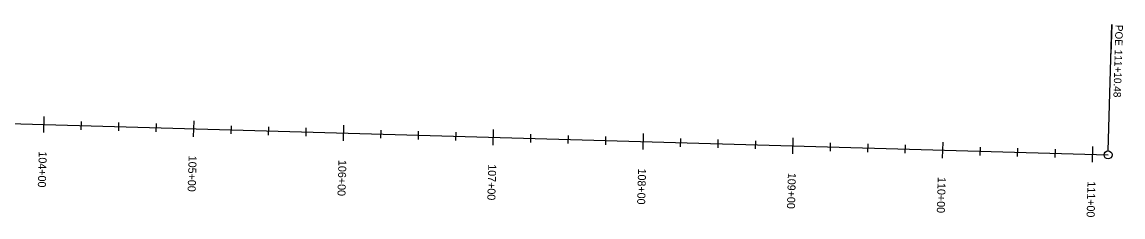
# Model space of a CAD drawing. Extents: x 2301963 to 2307911, y 760768 to 761974.
# Drawn here: x 2307177 to 2307911, y 760768 to 760898 of the extents above; entities that cross this region are included whole.
import ezdxf

# ---------------------------------------------------------------- set-up
doc = ezdxf.new("R2010")
doc.units = 0
for name, color, linetype in [('Default', 7, 'Continuous'), ('Draft_Station Cardinal Points', 7, 'Continuous'), ('Draft_Station Labels Major', 7, 'Continuous'), ('Draft_Station Ticks Major', 7, 'Continuous'), ('Draft_Station Ticks Minor', 7, 'Continuous'), ('Geom_Secondary', 7, 'Continuous')]:
    doc.layers.add(name, color=color, linetype=linetype)

msp = doc.modelspace()

# ---------------------------------------------------------------- linework, layer by layer
at = {"layer": 'Default'}
msp.add_line((2304792.58, 760898.19), (2307901.31, 760809.5), dxfattribs=at)
at = {"layer": 'Draft_Station Cardinal Points'}
for p, q in [((2307901.39, 760812.17), (2307903.79, 760896.47)), ((2307903.79, 760896.47), (2307903.23, 760876.79)), ((2307901.31, 760809.5), (2307901.31, 760809.5))]:
    msp.add_line(p, q, dxfattribs=at)
msp.add_circle((2307901.31, 760809.5), 2.67, dxfattribs=at)
at = {"layer": 'Draft_Station Ticks Major'}
for p, q in [((2307191.27, 760835.1), (2307190.97, 760824.48)), ((2307291.23, 760832.25), (2307290.93, 760821.63)), ((2307391.19, 760829.4), (2307390.89, 760818.78)), ((2307491.15, 760826.54), (2307490.84, 760815.93)), ((2307591.11, 760823.69), (2307590.8, 760813.08)), ((2307691.07, 760820.84), (2307690.76, 760810.23)), ((2307791.03, 760817.99), (2307790.72, 760807.37)), ((2307890.98, 760815.14), (2307890.68, 760804.52))]:
    msp.add_line(p, q, dxfattribs=at)
at = {"layer": 'Draft_Station Ticks Minor'}
for p, q in [((2307216.19, 760831.81), (2307216.03, 760826.29)), ((2307241.18, 760831.1), (2307241.02, 760825.58)), ((2307266.17, 760830.38), (2307266.01, 760824.86)), ((2307316.15, 760828.96), (2307315.99, 760823.44)), ((2307341.13, 760828.24), (2307340.98, 760822.73)), ((2307366.12, 760827.53), (2307365.97, 760822.01)), ((2307416.1, 760826.1), (2307415.95, 760820.59)), ((2307441.09, 760825.39), (2307440.94, 760819.87)), ((2307466.08, 760824.68), (2307465.93, 760819.16)), ((2307516.06, 760823.25), (2307515.91, 760817.73)), ((2307541.05, 760822.54), (2307540.9, 760817.02)), ((2307566.04, 760821.83), (2307565.89, 760816.31)), ((2307616.02, 760820.4), (2307615.87, 760814.88)), ((2307641.01, 760819.69), (2307640.86, 760814.17)), ((2307666, 760818.98), (2307665.85, 760813.46)), ((2307715.98, 760817.55), (2307715.82, 760812.03)), ((2307740.97, 760816.84), (2307740.81, 760811.32)), ((2307765.96, 760816.12), (2307765.8, 760810.61)), ((2307815.94, 760814.7), (2307815.78, 760809.18)), ((2307840.93, 760813.98), (2307840.77, 760808.47)), ((2307865.92, 760813.27), (2307865.76, 760807.75))]:
    msp.add_line(p, q, dxfattribs=at)
at = {"layer": 'Geom_Secondary'}
msp.add_line((2304792.58, 760898.19), (2307901.31, 760809.5), dxfattribs=at)

# ---------------------------------------------------------------- texts
at = {"layer": 'Draft_Station Cardinal Points'}
for s, p in [('POE ', (2307906.28, 760896.39)), ('111+10.48', (2307905.8, 760879.71))]:
    msp.add_text(s, height=5, rotation=268.36584, dxfattribs=at).set_placement(p)
at = {"layer": 'Draft_Station Labels Major'}
for s, p in [('104+00', (2307187.93, 760811.85)), ('105+00', (2307287.89, 760808.99)), ('106+00', (2307387.85, 760806.14)), ('107+00', (2307487.81, 760803.29)), ('108+00', (2307587.77, 760800.44)), ('109+00', (2307687.73, 760797.59)), ('110+00', (2307787.69, 760794.73)), ('111+00', (2307887.65, 760791.88))]:
    msp.add_text(s, height=5.34, rotation=268.36584, dxfattribs=at).set_placement(p)

doc.saveas('drawing.dxf')
